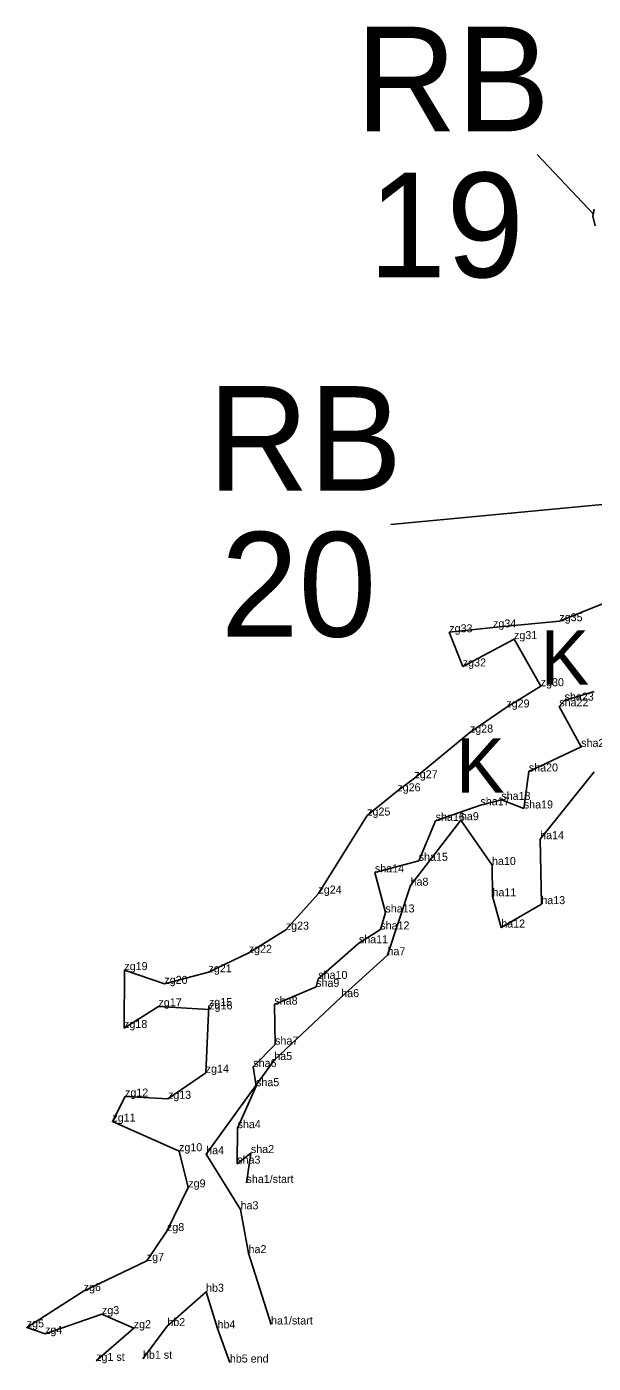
# Model space of a CAD drawing. Extents: x 2072529 to 2268796, y 436423 to 470406.
# Drawn here: x 2217317 to 2217671, y 438020 to 438855 of the extents above; entities that cross this region are included whole.
import ezdxf

# ---------------------------------------------------------------- set-up
doc = ezdxf.new("R2010")
doc.units = 0
for name, color, linetype in [('Default', 7, 'Continuous'), ('Exist Environmental Wetland Boundary Cogo Comment', 7, 'Continuous'), ('Exist Environmental Wetland Boundary Cogo Point CELL', 7, 'Continuous'), ('Exist Hydro Jurisdictional Stream or Body of Water NEU Mitigable Cogo Comment', 7, 'Continuous'), ('Old_Level_20', 7, 'Continuous'), ('Old_Level_52', 7, 'Continuous')]:
    doc.layers.add(name, color=color, linetype=linetype)

msp = doc.modelspace()

# ---------------------------------------------------------------- linework, layer by layer
at = {"layer": 'Default'}
for p, q in [((2217636.33, 438774.91), (2217671.41, 438737.63)), ((2217544.84, 438543.82), (2217741.11, 438562.25))]:
    msp.add_line(p, q, dxfattribs=at)
at = {"layer": 'Old_Level_20'}
for p, q in [((2217671, 438736.35), (2217671, 438736.35)), ((2217581.34, 438476.45), (2217581.34, 438476.45)), ((2217608.66, 438479.49), (2217608.66, 438479.49)), ((2217650.1, 438483.36), (2217650.1, 438483.36)), ((2217621.77, 438472.21), (2217621.77, 438472.21)), ((2217589.75, 438455.1), (2217589.75, 438455.1)), ((2217638.44, 438442.8), (2217638.44, 438442.8)), ((2217616.96, 438429.52), (2217616.96, 438429.52)), ((2217650.03, 438430.19), (2217650.03, 438430.19)), ((2217653.35, 438433.79), (2217653.35, 438433.79)), ((2217594.21, 438413.84), (2217594.21, 438413.84)), ((2217663.72, 438404.86), (2217663.72, 438404.86)), ((2217559.58, 438385.27), (2217559.58, 438385.27)), ((2217631.01, 438389.51), (2217631.01, 438389.51)), ((2217548.87, 438377.12), (2217548.87, 438377.12)), ((2217600.81, 438368.38), (2217600.81, 438368.38)), ((2217613.85, 438371.78), (2217613.85, 438371.78)), ((2217530.04, 438362), (2217530.04, 438362)), ((2217627.9, 438366.42), (2217627.9, 438366.42)), ((2217572.81, 438358.68), (2217572.81, 438358.68)), ((2217588.6, 438359.09), (2217588.6, 438359.09)), ((2217638.07, 438347.23), (2217638.07, 438347.23)), ((2217534.89, 438326.49), (2217534.89, 438326.49)), ((2217562.24, 438333.72), (2217562.24, 438333.72)), ((2217608.03, 438331.09), (2217608.03, 438331.09)), ((2217557.15, 438318.2), (2217557.15, 438318.2)), ((2217499.62, 438313.24), (2217499.62, 438313.24)), ((2217608.32, 438311.53), (2217608.32, 438311.53)), ((2217541.44, 438301.46), (2217541.44, 438301.46)), ((2217638.84, 438306.65), (2217638.84, 438306.65)), ((2217479.17, 438290.69), (2217479.17, 438290.69)), ((2217538.27, 438290.82), (2217538.27, 438290.82)), ((2217613.81, 438292.02), (2217613.81, 438292.02)), ((2217456.04, 438276.24), (2217456.04, 438276.24)), ((2217524.89, 438282.22), (2217524.89, 438282.22)), ((2217542.75, 438274.72), (2217542.75, 438274.72)), ((2217378.39, 438265.45), (2217378.39, 438265.45)), ((2217430.95, 438264.05), (2217430.95, 438264.05)), ((2217499.49, 438259.95), (2217499.49, 438259.95)), ((2217403.37, 438256.85), (2217403.37, 438256.85)), ((2217498.17, 438255.01), (2217498.17, 438255.01)), ((2217399.71, 438242.81), (2217399.71, 438242.81)), ((2217431.18, 438243.02), (2217431.18, 438243.02)), ((2217472.09, 438243.91), (2217472.09, 438243.91)), ((2217513.81, 438248.55), (2217513.81, 438248.55)), ((2217431.39, 438240.86), (2217431.39, 438240.86)), ((2217378.18, 438229.27), (2217378.18, 438229.27)), ((2217472.53, 438218.92), (2217472.53, 438218.92)), ((2217429.18, 438201.37), (2217429.18, 438201.37)), ((2217458.93, 438204.92), (2217458.93, 438204.92)), ((2217472.02, 438209.27), (2217472.02, 438209.27)), ((2217460.65, 438192.95), (2217460.65, 438192.95)), ((2217378.79, 438186.45), (2217378.79, 438186.45)), ((2217405.61, 438185.03), (2217405.61, 438185.03)), ((2217370.89, 438170.82), (2217370.89, 438170.82)), ((2217449.1, 438166.71), (2217449.1, 438166.71)), ((2217412.54, 438152.3), (2217412.54, 438152.3)), ((2217457.43, 438151.16), (2217457.43, 438151.16)), ((2217429.47, 438150.45), (2217429.47, 438150.45)), ((2217448.88, 438144.53), (2217448.88, 438144.53)), ((2217418.31, 438129.74), (2217418.31, 438129.74)), ((2217454.67, 438132.47), (2217454.67, 438132.47)), ((2217450.96, 438116), (2217450.96, 438116)), ((2217404.98, 438102.44), (2217404.98, 438102.44)), ((2217455.94, 438088.64), (2217455.94, 438088.64)), ((2217392.43, 438083.82), (2217392.43, 438083.82)), ((2217352.95, 438064.93), (2217352.95, 438064.93)), ((2217429.43, 438064.51), (2217429.43, 438064.51)), ((2217364.39, 438050.54), (2217364.39, 438050.54)), ((2217405.22, 438043.1), (2217405.22, 438043.1)), ((2217470.02, 438044.07), (2217470.02, 438044.07)), ((2217317.4, 438042.28), (2217317.4, 438042.28)), ((2217328.86, 438038.23), (2217328.86, 438038.23)), ((2217384.23, 438041.77), (2217384.23, 438041.77)), ((2217436.57, 438041.67), (2217436.57, 438041.67)), ((2217360.74, 438021.36), (2217360.74, 438021.36)), ((2217389.99, 438022.67), (2217389.99, 438022.67)), ((2217444.28, 438020.29), (2217444.28, 438020.29))]:
    msp.add_line(p, q, dxfattribs=at)
for points in [[(2217672.46, 438730.32), (2217671, 438736.35), (2217671.78, 438740.85)], [(2217360.74, 438021.36), (2217384.23, 438041.77), (2217364.39, 438050.54), (2217328.86, 438038.23), (2217317.4, 438042.28), (2217352.95, 438064.93), (2217392.43, 438083.82), (2217404.98, 438102.44), (2217418.31, 438129.74), (2217412.54, 438152.3), (2217370.89, 438170.82), (2217378.79, 438186.45), (2217405.61, 438185.03), (2217429.18, 438201.37), (2217431.18, 438243.02), (2217431.39, 438240.86), (2217399.71, 438242.81), (2217378.18, 438229.27), (2217378.39, 438265.45), (2217403.37, 438256.85), (2217430.95, 438264.05), (2217456.04, 438276.24), (2217479.17, 438290.69), (2217499.62, 438313.24), (2217530.04, 438362), (2217548.87, 438377.12), (2217559.58, 438385.27), (2217594.21, 438413.84), (2217616.96, 438429.52), (2217638.44, 438442.8), (2217621.77, 438472.21), (2217589.75, 438455.1), (2217581.34, 438476.45), (2217608.66, 438479.49), (2217650.1, 438483.36), (2217676.96, 438494.19)], [(2217671.8, 438389.27), (2217638.07, 438347.23), (2217638.84, 438306.65), (2217613.81, 438292.02), (2217608.32, 438311.53), (2217608.03, 438331.09), (2217588.6, 438359.09), (2217557.15, 438318.2), (2217542.75, 438274.72), (2217513.81, 438248.55), (2217472.02, 438209.27), (2217429.47, 438150.45), (2217450.96, 438116), (2217455.94, 438088.64), (2217470.02, 438044.07)], [(2217389.99, 438022.67), (2217405.22, 438043.1), (2217429.43, 438064.51), (2217436.57, 438041.67), (2217444.28, 438020.29)]]:
    msp.add_lwpolyline(points, dxfattribs=at)
at = {"layer": 'Old_Level_52'}
msp.add_lwpolyline([(2217454.67, 438132.47), (2217457.43, 438151.16), (2217448.88, 438144.53), (2217449.1, 438166.71), (2217460.65, 438192.95), (2217458.93, 438204.92), (2217472.53, 438218.92), (2217472.09, 438243.91), (2217498.17, 438255.01), (2217499.49, 438259.95), (2217524.89, 438282.22), (2217538.27, 438290.82), (2217541.44, 438301.46), (2217534.89, 438326.49), (2217562.24, 438333.72), (2217572.81, 438358.68), (2217600.81, 438368.38), (2217613.85, 438371.78), (2217627.9, 438366.42), (2217631.01, 438389.51), (2217663.72, 438404.86), (2217650.03, 438430.19), (2217653.35, 438433.79), (2217671.77, 438439.56)], dxfattribs=at)

# ---------------------------------------------------------------- texts
at = {"layer": 'Default'}
for s, p in [('RB', (2217522.83, 438789.38)), ('19', (2217530.88, 438698.24)), ('RB', (2217430.54, 438564.89)), ('20', (2217438.59, 438473.74))]:
    msp.add_text(s, height=65.34, dxfattribs=at).set_placement(p)
at = {"layer": 'Exist Environmental Wetland Boundary Cogo Comment'}
for s, p in [('zg35', (2217650.1, 438483.36)), ('zg33', (2217581.34, 438476.45)), ('zg34', (2217608.66, 438479.49)), ('zg31', (2217621.77, 438472.21)), ('zg32', (2217589.75, 438455.1)), ('zg30', (2217638.44, 438442.8)), ('zg29', (2217616.96, 438429.52)), ('zg28', (2217594.21, 438413.84)), ('zg27', (2217559.58, 438385.27)), ('zg26', (2217548.87, 438377.12)), ('zg25', (2217530.04, 438362)), ('ha9', (2217588.6, 438359.09)), ('ha14', (2217638.07, 438347.23)), ('ha10', (2217608.03, 438331.09)), ('zg24', (2217499.62, 438313.24)), ('ha8', (2217557.15, 438318.2)), ('ha11', (2217608.32, 438311.53)), ('ha13', (2217638.84, 438306.65)), ('zg23', (2217479.17, 438290.69)), ('ha12', (2217613.81, 438292.02)), ('zg22', (2217456.04, 438276.24)), ('ha7', (2217542.75, 438274.72)), ('zg19', (2217378.39, 438265.45)), ('zg21', (2217430.95, 438264.05)), ('zg20', (2217403.37, 438256.85)), ('ha6', (2217513.81, 438248.55)), ('zg17', (2217399.71, 438242.81)), ('zg15', (2217431.18, 438243.02)), ('zg16', (2217431.39, 438240.86)), ('zg18', (2217378.18, 438229.27)), ('ha5', (2217472.02, 438209.27)), ('zg14', (2217429.18, 438201.37)), ('zg12', (2217378.79, 438186.45)), ('zg13', (2217405.61, 438185.03)), ('zg11', (2217370.89, 438170.82)), ('zg10', (2217412.54, 438152.3)), ('ha4', (2217429.47, 438150.45)), ('zg9', (2217418.31, 438129.74)), ('ha3', (2217450.96, 438116)), ('zg8', (2217404.98, 438102.44)), ('ha2', (2217455.94, 438088.64)), ('zg7', (2217392.43, 438083.82)), ('zg6', (2217352.95, 438064.93)), ('hb3', (2217429.43, 438064.51)), ('zg3', (2217364.39, 438050.54)), ('zg5', (2217317.4, 438042.28)), ('zg4', (2217328.86, 438038.23)), ('zg2', (2217384.23, 438041.77)), ('hb2', (2217405.22, 438043.1)), ('hb4', (2217436.57, 438041.67)), ('ha1/start', (2217470.02, 438044.07)), ('zg1 st', (2217360.74, 438021.36)), ('hb1 st', (2217389.99, 438022.67)), ('hb5 end', (2217444.28, 438020.29))]:
    msp.add_text(s, height=5, dxfattribs=at).set_placement(p)
at = {"layer": 'Exist Environmental Wetland Boundary Cogo Point CELL'}
for p in [(2217638.42, 438443.72), (2217585.63, 438376.25)]:
    msp.add_text('K', height=34, dxfattribs=at).set_placement(p)
at = {"layer": 'Exist Hydro Jurisdictional Stream or Body of Water NEU Mitigable Cogo Comment'}
for s, p in [('sha22', (2217650.03, 438430.19)), ('sha23', (2217653.35, 438433.79)), ('sha21', (2217663.72, 438404.86)), ('sha20', (2217631.01, 438389.51)), ('sha18', (2217613.85, 438371.78)), ('sha17', (2217600.81, 438368.38)), ('sha19', (2217627.9, 438366.42)), ('sha16', (2217572.81, 438358.68)), ('sha15', (2217562.24, 438333.72)), ('sha14', (2217534.89, 438326.49)), ('sha13', (2217541.44, 438301.46)), ('sha12', (2217538.27, 438290.82)), ('sha11', (2217524.89, 438282.22)), ('sha9', (2217498.17, 438255.01)), ('sha10', (2217499.49, 438259.95)), ('sha8', (2217472.09, 438243.91)), ('sha7', (2217472.53, 438218.92)), ('sha6', (2217458.93, 438204.92)), ('sha5', (2217460.65, 438192.95)), ('sha4', (2217449.1, 438166.71)), ('sha2', (2217457.43, 438151.16)), ('sha3', (2217448.88, 438144.53)), ('sha1/start', (2217454.67, 438132.47))]:
    msp.add_text(s, height=5, dxfattribs=at).set_placement(p)

doc.saveas('drawing.dxf')
